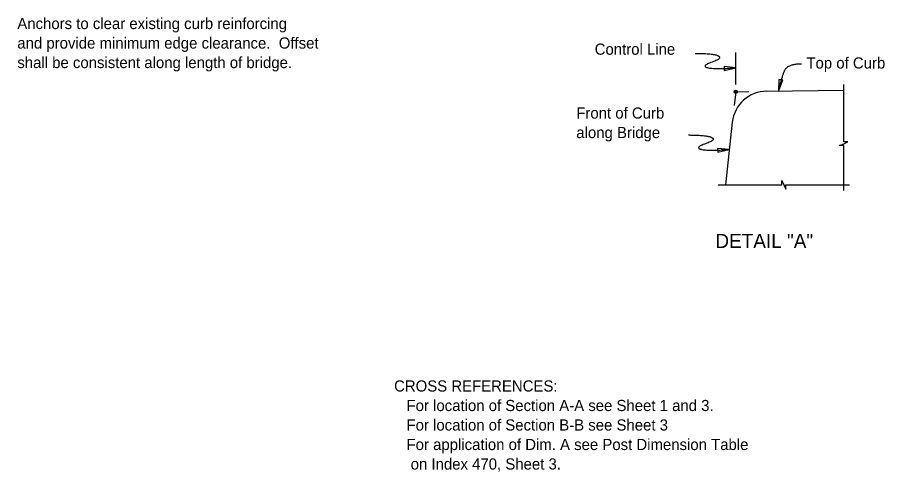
# Model space of a CAD drawing. Extents: x 21629.5 to 21698.8, y 56199.4 to 56237.6.
# Drawn here: x 21650.67 to 21666.33, y 56210.31 to 56218.51 of the extents above; entities that cross this region are included whole.
import ezdxf

# ---------------------------------------------------------------- set-up
doc = ezdxf.new("R2010")
doc.units = 0
for name, color, linetype in [('Dimension', 7, 'Continuous'), ('ExistSuperStruct', 7, 'Continuous'), ('TextStructures', 7, 'Continuous')]:
    doc.layers.add(name, color=color, linetype=linetype)

msp = doc.modelspace()

# ---------------------------------------------------------------- linework, layer by layer
at = {"layer": 'Dimension'}
for p, q in [((21663.637, 56217.301), (21663.637, 56217.879)), ((21663.637, 56217.171), (21663.609, 56216.922)), ((21663.637, 56217.171), (21663.874, 56217.174))]:
    msp.add_line(p, q, dxfattribs=at)
for points in [[(21663.637, 56217.601), (21663.427, 56217.626), (21663.43, 56217.556)], [(21664.411, 56217.182), (21664.487, 56217.379), (21664.418, 56217.393)], [(21663.52, 56216.127), (21663.31, 56216.148), (21663.314, 56216.078)]]:
    msp.add_lwpolyline(points, close=True, dxfattribs=at)
for points in [[(21665.587, 56215.387), (21665.587, 56216.198), (21665.509, 56216.198), (21665.587, 56216.232), (21665.664, 56216.266), (21665.587, 56216.266), (21665.587, 56217.303)], [(21663.32, 56215.492), (21664.472, 56215.492), (21664.472, 56215.569), (21664.506, 56215.492), (21664.54, 56215.414), (21664.54, 56215.492), (21665.692, 56215.492)]]:
    msp.add_lwpolyline(points, dxfattribs=at)
for radius in [0.0299, 0.0196, 0.00888]:
    msp.add_circle((21663.637, 56217.17), radius, dxfattribs=at)
for points in [[(21662.903, 56217.863), (21663.24, 56217.863), (21663.406, 56217.772), (21663.015, 56217.638), (21663.229, 56217.574), (21663.637, 56217.601)], [(21664.828, 56217.67), (21664.578, 56217.67), (21664.465, 56217.446), (21664.411, 56217.182)], [(21662.786, 56216.389), (21663.123, 56216.389), (21663.289, 56216.298), (21662.898, 56216.164), (21663.113, 56216.1), (21663.52, 56216.127)]]:
    msp.add_open_spline(points, degree=2, dxfattribs=at)
at = {"layer": 'ExistSuperStruct'}
for p, q in [((21664.197, 56217.179), (21665.587, 56217.198)), ((21663.576, 56216.623), (21663.45, 56215.492))]:
    msp.add_line(p, q, dxfattribs=at)
msp.add_arc((21664.197, 56216.554), 0.625, 90, 173.6598, dxfattribs=at)

# ---------------------------------------------------------------- texts
at = {"layer": 'Dimension'}
for s, p in [('Anchors to clear existing curb reinforcing', (21650.666, 56218.301)), ('and provide minimum edge clearance.  Offset', (21650.666, 56217.949)), ('shall be consistent along length of bridge.', (21650.666, 56217.597)), ('Front of Curb', (21660.759, 56216.685)), ('along Bridge', (21660.759, 56216.333)), ('CROSS REFERENCES:', (21657.469, 56211.757)), ('   For location of Section A-A see Sheet 1 and 3.', (21657.469, 56211.405)), ('   For location of Section B-B see Sheet 3', (21657.469, 56211.053)), ('   For application of Dim. A see Post Dimension Table ', (21657.469, 56210.701)), ('    on Index 470, Sheet 3.', (21657.469, 56210.349))]:
    msp.add_text(s, height=0.2016, dxfattribs=at).set_placement(p)
at = {"layer": 'TextStructures'}
for s, height, p in [('Control Line', 0.2016, (21661.091, 56217.838)), ('Top of Curb', 0.2016, (21664.914, 56217.589)), ('DETAIL "A"', 0.256, (21663.27, 56214.348))]:
    msp.add_text(s, height=height, dxfattribs=at).set_placement(p)

doc.saveas('drawing.dxf')
